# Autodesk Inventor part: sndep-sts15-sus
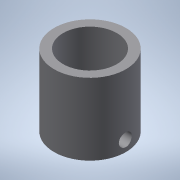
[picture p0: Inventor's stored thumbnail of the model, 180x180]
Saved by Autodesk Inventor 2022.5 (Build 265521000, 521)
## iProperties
Created: 2016-12
Part Number: sndep-sts15-sus
Material: 一般
Document SubType Name: Modeling
Designer: imaocorp
Density: 1 g/cm^3
Appearance: 既定
Author: imaocorp
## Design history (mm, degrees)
node "sndep-sts15-sus.x_t1"
node "sndep-sts15-sus"
node "Base1"
